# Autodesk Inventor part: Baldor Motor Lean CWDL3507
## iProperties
Shininess: 64.0
Length Units: 11272
Angle Units: 11279
Time Units: 11290
Mass Units: 11286
Length Display Precision: 3
Angle Display Precision: 2
Compacted: True
Part Number: Baldor Motor Lean CWDL3507
Document SubType Name: Modeling
Created: 2003-11
Designer: Larry Caldwell
Material: Steel CRS
Manufacturer: Standard
Standards Organization: Custom
Description: 3/4 Hp 56C
Density: 0.0
Volumn: 0.0
Area: 0.0
PropertySet Name: Model Information
Control State: 0
Master: False
Checked Out: False
d55: 0.060 in
SaveDate: 2003-11-22
SaveTime: 10:54
TotalMass: 125.145 lbmass
TotalVolume: 440.714 in^3
Author: Larry Caldwell
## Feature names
1. Revolution1
2. Revolution2
3. Extrusion1
4. Fillet1
5. Extrusion2
6. Fillet2
7. Extrusion3
8. Extrusion4
9. Extrusion5
10. Fillet3
11. Fillet4
12. Extrusion6
13. Extrusion7
14. Extrusion8
15. Fillet5
16. Fillet6
17. Extrusion9
18. Extrusion10
19. Fillet7
20. Fillet8
21. Extrusion11
22. Hole1
